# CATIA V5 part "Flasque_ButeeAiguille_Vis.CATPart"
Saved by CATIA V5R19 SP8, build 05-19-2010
Part number: Flasque_ButéeAiguilles.1
Nomenclature: 70_f
Bounding box of the stored display mesh (mm): x -12.5 to 12.5, y -12.5 to 12.5, z 0 to 1
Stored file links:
  C:\Users\rphgr\Desktop\0_Tapis_TC520B_vitesse\Flasque_ButeeAiguille_Vis.CATPart
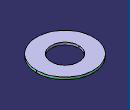
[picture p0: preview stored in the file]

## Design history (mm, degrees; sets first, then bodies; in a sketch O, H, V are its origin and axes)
Body1 (main body)
  AxisSystem1: origin (0, 0, 0), X (1, 0, 0), Y (0, 1, 0), Z (0, 0, 1)
  Sketch1 on XY plane of AxisSystem1, origin (0, 0, 0), H (1, 0, 0), V (0, 1, 0)
    circle A1 centre (0, 0) radius 6.1
    circle A2 centre (0, 0) radius 12.5
    radius A1 = 6.1
    radius A2 = 12.5
  Pad1: profile Sketch1, direction (0, 0, 1), length 1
